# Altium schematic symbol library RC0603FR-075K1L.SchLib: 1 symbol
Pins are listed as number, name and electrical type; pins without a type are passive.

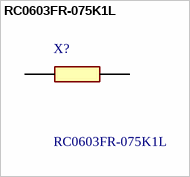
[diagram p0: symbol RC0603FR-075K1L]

## RC0603FR-075K1L
designator X?
Thick Film Resistors - SMD 5.1K OHM 1%; Manufacturer_Name: Yageo Group; Geometry.Height: 0.55mm
footprint RESC1608X55N
pins: 1, 2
